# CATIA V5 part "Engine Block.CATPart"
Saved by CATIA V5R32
Part number: Part1
Bounding box of the stored display mesh (mm): x 0 to 150, y 0 to 40, z 0 to 43
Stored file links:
  D:\PROJECTS\Project 2022\CATIA V5 6R 2022\Resources\Tutorial Files\c19_catia_v5_6r2022_tut\C19_tut_04.CATPart\Engine Block.CATPart
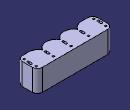
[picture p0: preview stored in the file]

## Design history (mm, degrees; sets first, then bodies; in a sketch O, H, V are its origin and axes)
Body1 (main body)
  Sketch1 on xy-plane, origin (0, 0, 0), H (1, 0, 0), V (0, 1, 0)
    line L1 (10, 0) -> (140, 0)
    line L2 (150, 10) -> (150, 30)
    line L3 (140, 40) -> (10, 40)
    line L4 (0, 30) -> (0, 10)
    arc A1 centre (10, 10) radius 10 from (10, 0) to (0, 10) cw
    arc A2 centre (140, 10) radius 10 from (140, 0) to (150, 10) ccw
    arc A3 centre (140, 30) radius 10 from (150, 30) to (140, 40) ccw
    arc A4 centre (10, 30) radius 10 from (10, 40) to (0, 30) ccw
    radius A1 = 10
    radius A2 = 10
    radius A3 = 10
    radius A4 = 10
    distance L2 L4 = 150
    distance L3 L1 = 40
    horizontal: L1 H, L3 H
    vertical: L2 V, L4 V
    coincidence: L1 O, L4 O
    tangency: A1 L1, A1 L4, A2 L1, A2 L2, A3 L2, A3 L3, A4 L3, A4 L4
  Pad1: profile Sketch1, direction (0, 0, 1), length 43
  Sketch2 on xy-plane, origin (0, 0, 0), H (1, 0, 0), V (0, 1, 0)
    circle A1 centre (22.5, 20) radius 12.5
    point P1 (22.5, 20)
    point P2 (57.5, 20)
    circle A2 centre (57.5, 20) radius 12.5
    point P3 (92.5, 20)
    circle A3 centre (92.5, 20) radius 12.5
    point P4 (127.5, 20)
    circle A4 centre (127.5, 20) radius 12.5
    reference projected line E1 (140, 40) -> (10, 40) from edge [face of Pad1 from Sketch1.L3 | end face of Pad1]
    construction line L1 (22.5, 20) -> (160.4972, 20)
    axis line L2 (75, 83.7885) -> (75, -11.6317)
    reference projected line E2 (150, 10) -> (150, 30) from edge [face of Pad1 from Sketch1.L2 | end face of Pad1]
    reference projected line E3 (0, 30) -> (0, 10) from edge [face of Pad1 from Sketch1.L4 | end face of Pad1]
    radius A2 = 12.5
    radius A3 = 12.5
    radius A4 = 12.5
    distance P1 E1 = 20
    distance P1 P2 = 35
    distance P2 P3 = 35
    distance P3 P4 = 35
    horizontal: L1 H
    coincidence: L1 P2, L1 P3, P4 L1
    symmetry: E2 E3 L2, A4 A1 L2
  Pocket1: profile Sketch2, direction (0, 0, 1), length 40
  Sketch3 on start face of Pad1, origin (0, 0, 0), H (1, 0, 0), V (0, -1, 0)
    arc A1 centre (22.5, -20) radius 20 from (40, -10.3175) to (22.4999, 0) ccw
    arc A2 centre (57.5, -20) radius 20 from (57.5, 0) to (40, -10.3175) ccw
    reference projected circle E1 centre (57.5, -20) radius 12.5 from edge [face of Pocket1 from Sketch2.A2 | start face of Pad1]
    reference projected circle E2 centre (22.5, -20) radius 12.5 from edge [face of Pocket1 from Sketch2.A1 | start face of Pad1]
    line L1 (22.4999, 0) -> (57.5, 0)
    radius A1 = 20
    radius A2 = 20
    concentricity: A2 E1, E2 A1
    fix: L1
  Pocket2: profile Sketch3, direction (0, 0, 1), through (limit type 6)
  RectPattern1: of Pocket2, direction 1 instances 3, spacing 35, along edge [start face of Pad1 | face of Pad1 from Sketch1.L1]
  Sketch4 on start face of Pad1, origin (0, 0, 0), H (1, 0, 0), V (0, -1, 0)
    circle A1 centre (6, -32) radius 2
    point P2 (40, -32)
    circle A2 centre (40, -32) radius 2
    point P3 (75, -32)
    circle A3 centre (75, -32) radius 2
    point P4 (110, -32)
    circle A4 centre (110, -32) radius 2
    circle A5 centre (144, -32) radius 2
    construction line L1 (6, -32) -> (144, -32)
    construction line L2 (40, 4.6658) -> (40, -59.1562)
    reference projected point E1 (40, -10.3175) from vertex [start face of Pad1 | face of Pocket2 from Sketch3.A2 | face of Pocket2 from Sketch3.A1]
    construction line L3 (110, 9.612) -> (110, -55.4864)
    construction line L4 (75, 52.0631) -> (75, -75.4722)
    reference projected line E2 (0, -30) -> (0, -10) from edge [start face of Pad1 | face of Pad1 from Sketch1.L4]
    reference projected line E3 (150, -10) -> (150, -30) from edge [start face of Pad1 | face of Pad1 from Sketch1.L2]
    reference projected point E4 (110, -10.3175) from vertex [face of RectPattern1 | face of RectPattern1 | start face of Pad1]
    axis line L5 (-9.2648, -20) -> (155.2665, -20)
    reference projected line E5 (10, 0) -> (140, 0) from edge [start face of Pad1 | face of Pad1 from Sketch1.L1]
    reference projected line E6 (140, -40) -> (10, -40) from edge [start face of Pad1 | face of Pad1 from Sketch1.L3]
    circle A6 centre (6, -8) radius 2
    circle A7 centre (144, -8) radius 2
    radius A1 = 2
    radius A2 = 2
    radius A3 = 2
    radius A4 = 2
    horizontal: L1 H, L5 H
    coincidence: P4 L1, P3 L1, P2 L1, L2 E1, P2 L2, P4 L3, P3 L4, L3 E4
    vertical: L2 V, L3 V, L4 V
    symmetry: E2 E3 L4, A1 A5 L4, E5 E6 L5, A1 A6 L5, A5 A7 L5
    fix: A1
  Pocket3: profile Sketch4, direction (0, 0, 1), through (limit type 6)
  Sketch5 on start face of Pad1, origin (0, 0, 0), H (1, 0, 0), V (0, -1, 0)
    construction line L1 (40, -22.3175) -> (40, -16.3175)
    point P2 (40, -16.3175)
    line L2 (38, -22.3175) -> (38, -16.3175)
    line L3 (42, -16.3175) -> (42, -22.3175)
    arc A1 centre (40, -16.3175) radius 2 from (38, -16.3175) to (42, -16.3175) cw
    arc A2 centre (40, -22.3175) radius 2 from (42, -22.3175) to (38, -22.3175) cw
    point P3 (38, -22.3175)
    point P4 (38, -16.3175)
    point P5 (42, -16.3175)
    point P6 (42, -22.3175)
    reference projected point E1 (40, -10.3175) from vertex [start face of Pad1 | face of Pocket2 from Sketch3.A2 | face of Pocket2 from Sketch3.A1]
    reference projected point E2 (40, -10.3175) from vertex [start face of Pad1 | face of Pocket2 from Sketch3.A2 | face of Pocket2 from Sketch3.A1]
    point P7 (75, -16.3175)
    point P8 (75, -22.3175)
    construction line L4 (75, -22.3175) -> (75, -16.3175)
    point P9 (73, -22.3175)
    point P10 (73, -16.3175)
    point P11 (77, -16.3175)
    point P12 (77, -22.3175)
    line L5 (73, -22.3175) -> (73, -16.3175)
    line L6 (77, -16.3175) -> (77, -22.3175)
    arc A3 centre (75, -16.3175) radius 2 from (73, -16.3175) to (77, -16.3175) cw
    arc A4 centre (75, -22.3175) radius 2 from (77, -22.3175) to (73, -22.3175) cw
    reference projected point E3 (75, -10.3175) from vertex [face of RectPattern1 | face of RectPattern1 | start face of Pad1]
    construction line L7 (110, -22.3175) -> (110, -16.3175)
    point P15 (112, -22.3175)
    point P16 (112, -16.3175)
    point P17 (108, -16.3175)
    point P18 (108, -22.3175)
    line L8 (112, -22.3175) -> (112, -16.3175)
    line L9 (108, -16.3175) -> (108, -22.3175)
    arc A5 centre (110, -16.3175) radius 2 from (112, -16.3175) to (108, -16.3175) ccw
    arc A6 centre (110, -22.3175) radius 2 from (108, -22.3175) to (112, -22.3175) ccw
    reference projected point E4 (75, -10.3175) from vertex [face of RectPattern1 | face of RectPattern1 | start face of Pad1]
    axis line L10 (40, -22.3175) -> (110, -22.3175)
    construction line L11 (5, -22.3175) -> (5, -16.3175)
    point P21 (7, -22.3175)
    point P22 (7, -16.3175)
    point P23 (3, -16.3175)
    point P24 (3, -22.3175)
    line L12 (7, -22.3175) -> (7, -16.3175)
    line L13 (3, -16.3175) -> (3, -22.3175)
    arc A7 centre (5, -16.3175) radius 2 from (7, -16.3175) to (3, -16.3175) ccw
    arc A8 centre (5, -22.3175) radius 2 from (3, -22.3175) to (7, -22.3175) ccw
    construction line L14 (145, -22.3175) -> (145, -16.3175)
    point P27 (147, -22.3175)
    point P28 (147, -16.3175)
    point P29 (143, -16.3175)
    point P30 (143, -22.3175)
    line L15 (147, -22.3175) -> (147, -16.3175)
    line L16 (143, -16.3175) -> (143, -22.3175)
    arc A9 centre (145, -16.3175) radius 2 from (147, -16.3175) to (143, -16.3175) ccw
    arc A10 centre (145, -22.3175) radius 2 from (143, -22.3175) to (147, -22.3175) ccw
    distance L1 L2 = 2
    length L1 = 6
    distance P2 E2 = 6
    distance P7 E4 = 6
    radius A3 = 2
    distance L5 L6 = 4
    vertical: L1 V
    tangency: A1 L2, A2 L2, A1 L3, A2 L3
    coincidence: L1 E1, L4 E3, L10 P8
    symmetry: L1 L7 L4, P3 P15 L4, P4 P16 L4, P5 P17 L4, P6 P18 L4, L2 L8 L4, L3 L9 L4, A1 A5 L4, A2 A6 L4, L4 L11 L1, P9 P21 L1, P10 P22 L1, P11 P23 L1, P12 P24 L1, L5 L12 L1, L6 L13 L1, A3 A7 L1, A4 A8 L1, L4 L14 L7, P9 P27 L7, P10 P28 L7, P11 P29 L7, P12 P30 L7, L5 L15 L7, L6 L16 L7, A3 A9 L7, A4 A10 L7
    horizontal: L10 H
  Pocket4: profile Sketch5, direction (0, 0, 1), through (limit type 6)
  Sketch6 on start face of Pad1, origin (0, 0, 0), H (1, 0, 0), V (0, -1, 0)
    construction line L1 (-2.1155, -20) -> (152.3983, -20)
    reference projected line E1 (10, 0) -> (140, 0) from edge [start face of Pad1 | face of Pad1 from Sketch1.L1]
    reference projected line E2 (140, -40) -> (10, -40) from edge [start face of Pad1 | face of Pad1 from Sketch1.L3]
    circle A1 centre (22, -4) radius 1.5
    point P3 (22, -4)
    circle A2 centre (22, -36) radius 1.5
    construction line L2 (40, 18.8361) -> (40, -51.6721)
    reference projected point E3 (40, -10.3175) from vertex [start face of Pad1 | face of RectPattern1 | face of Pocket2 from Sketch3.A1]
    circle A3 centre (58, -4) radius 1.5
    axis line L3 (75, 12.6867) -> (75, -50.2038)
    reference projected point E4 (75, -10.3175) from vertex [face of RectPattern1 | face of RectPattern1 | start face of Pad1]
    circle A4 centre (58, -36) radius 1.5
    circle A5 centre (128, -4) radius 1.5
    circle A6 centre (128, -36) radius 1.5
    circle A7 centre (92, -36) radius 1.5
    circle A8 centre (92, -4) radius 1.5
    radius A1 = 1.5
    distance P3 V = 22
    distance P3 L1 = 16
    horizontal: L1 H
    symmetry: E1 E2 L1, A1 A2 L1, A1 A3 L2, A2 A4 L2, A1 A5 L3, A2 A6 L3, A4 A7 L3, A3 A8 L3
    vertical: L2 V, L3 V
    coincidence: E3 L2, L3 E4
  Pocket5: profile Sketch6, direction (0, 0, 1), length 10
